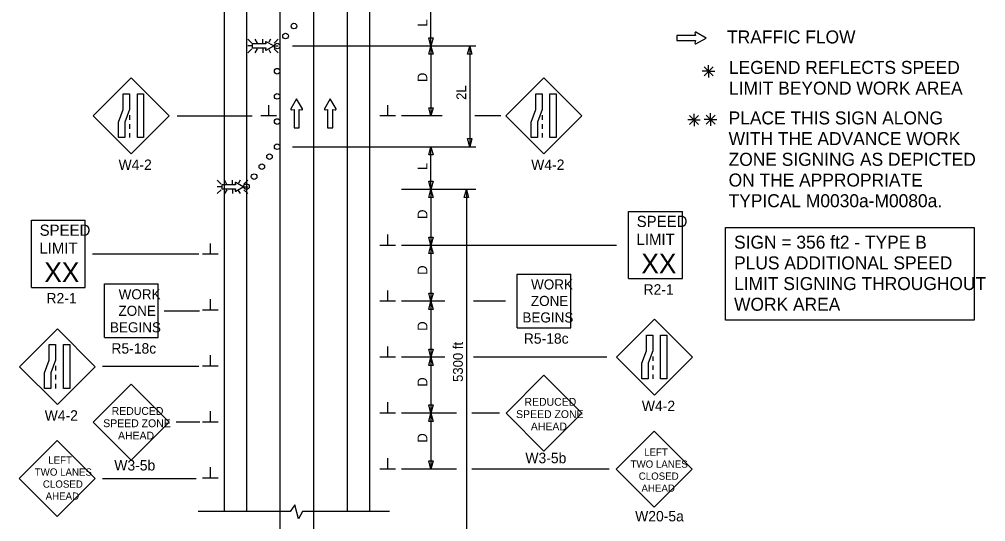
# Model space of a CAD drawing. Extents: x 16553 to 18475, y 5759 to 7026.
# Drawn here: x 16725 to 17417, y 6273 to 6632 of the extents above; entities that cross this region are included whole.
import ezdxf

# ---------------------------------------------------------------- set-up
doc = ezdxf.new("R2010")
doc.units = 0
for name, color, linetype in [('ALI_LEGAL_EX', 7, 'Continuous'), ('MT_SCRATCH_LEVEL_E', 7, 'Continuous'), ('PAVT_EDGE_EX', 7, 'Continuous'), ('TRAFFIC_SIGNS_PR', 7, 'Continuous'), ('TYPICAL_TEXT_DIMEN_EX', 7, 'Continuous'), ('TYPICAL_TEXT_DIMEN_PR', 7, 'Continuous')]:
    doc.layers.add(name, color=color, linetype=linetype)

msp = doc.modelspace()

# ---------------------------------------------------------------- linework, layer by layer
at = {"layer": 'ALI_LEGAL_EX'}
for p, q in [((16911.66, 7026.35), (16911.66, 6197.16)), ((16935.66, 7026.35), (16935.66, 6197.16)), ((16935.66, 7026.35), (16935.66, 6197.16))]:
    msp.add_line(p, q, dxfattribs=at)
for points in [[(16911.66, 6575.78), (16911.66, 6550.78)], [(16935.66, 6575.78), (16935.66, 6550.78)], [(16911.66, 6475.78), (16911.66, 6450.78)], [(16935.66, 6475.78), (16935.66, 6450.78)], [(16911.66, 6375.78), (16911.66, 6350.78)], [(16935.66, 6375.78), (16935.66, 6350.78)]]:
    msp.add_lwpolyline(points, dxfattribs=at)
at = {"layer": 'MT_SCRATCH_LEVEL_E'}
for p, q in [((17208.96, 6620.64), (17195.71, 6620.64)), ((17195.71, 6620.64), (17195.71, 6616.9)), ((17208.65, 6622.42), (17208.96, 6620.64)), ((17216.57, 6618.79), (17209.33, 6622.9)), ((17209.33, 6614.64), (17216.57, 6618.79)), ((17195.71, 6616.9), (17208.96, 6616.9)), ((17208.96, 6616.9), (17208.65, 6615.12)), ((16923.57, 6575.4), (16919.46, 6568.15)), ((16927.71, 6568.15), (16923.57, 6575.4)), ((16947.62, 6575.4), (16943.51, 6568.15)), ((16951.77, 6568.15), (16947.62, 6575.4)), ((16919.94, 6567.47), (16921.72, 6567.79)), ((16921.72, 6567.79), (16921.72, 6554.53)), ((16925.46, 6554.53), (16925.46, 6567.79)), ((16925.46, 6567.79), (16927.23, 6567.47)), ((16943.99, 6567.47), (16945.77, 6567.79)), ((16945.77, 6567.79), (16945.77, 6554.53)), ((16949.51, 6554.53), (16949.51, 6567.79)), ((16949.51, 6567.79), (16951.29, 6567.47)), ((16921.72, 6554.53), (16925.46, 6554.53)), ((16945.77, 6554.53), (16949.51, 6554.53))]:
    msp.add_line(p, q, dxfattribs=at)
for centre, start, end in [((17209.11, 6622.49), 60.42484, 189.96381), ((17209.11, 6615.05), 170.03619, 299.77312), ((16919.86, 6567.93), 150.42484, 279.96381), ((16927.3, 6567.93), 260.03619, 29.77312), ((16943.92, 6567.93), 150.42484, 279.96381), ((16951.36, 6567.93), 260.03619, 29.77312)]:
    msp.add_arc(centre, 0.463, start, end, dxfattribs=at)
at = {"layer": 'PAVT_EDGE_EX'}
for p, q in [((16871.66, 6926.66), (16871.66, 6280.21)), ((16887.66, 6926.66), (16887.66, 6280.21)), ((16959.66, 6926.66), (16959.66, 6280.21)), ((16975.66, 6926.66), (16975.66, 6280.21))]:
    msp.add_line(p, q, dxfattribs=at)
at = {"layer": 'TRAFFIC_SIGNS_PR'}
for p, q in [((16891.44, 6615.16), (16888.62, 6617.99)), ((16893.74, 6617.98), (16895.36, 6615.16)), ((16899.52, 6615.16), (16899.52, 6617.98)), ((16904.99, 6617.98), (16903.79, 6615.89)), ((16910.43, 6617.98), (16907.61, 6615.16)), ((16891.44, 6613.13), (16888.62, 6613.13)), ((16891.44, 6611.1), (16888.62, 6608.28)), ((16895.39, 6611.1), (16893.76, 6608.28)), ((16899.52, 6611.1), (16899.52, 6608.28)), ((16907.61, 6613.13), (16910.43, 6613.13)), ((16910.43, 6608.28), (16907.61, 6611.1)), ((16903.71, 6610.47), (16904.97, 6608.28)), ((16805.2, 6590.2), (16778.05, 6563.05)), ((16832.35, 6563.05), (16805.2, 6590.2)), ((17100.49, 6590.2), (17073.34, 6563.05)), ((17127.65, 6563.05), (17100.49, 6590.2)), ((16778.05, 6563.05), (16805.2, 6535.9)), ((16803.95, 6563.54), (16803.95, 6560.34)), ((16805.2, 6535.9), (16832.35, 6563.05)), ((17073.34, 6563.05), (17100.49, 6535.89)), ((17099.25, 6563.54), (17099.25, 6560.34)), ((17100.49, 6535.89), (17127.65, 6563.05)), ((16803.95, 6557.14), (16803.95, 6553.94)), ((17099.25, 6557.14), (17099.25, 6553.94)), ((16803.95, 6550.74), (16803.95, 6547.54)), ((17099.25, 6550.74), (17099.25, 6547.54)), ((16869.6, 6514.38), (16866.78, 6517.2)), ((16871.9, 6517.2), (16873.52, 6514.38)), ((16877.68, 6514.38), (16877.68, 6517.2)), ((16883.15, 6517.2), (16881.94, 6515.1)), ((16888.59, 6517.19), (16885.77, 6514.38)), ((16869.6, 6512.34), (16866.78, 6512.34)), ((16869.6, 6510.31), (16866.78, 6507.49)), ((16873.55, 6510.31), (16871.92, 6507.49)), ((16877.68, 6510.31), (16877.68, 6507.49)), ((16881.87, 6509.68), (16883.13, 6507.49)), ((16885.77, 6512.34), (16888.59, 6512.34)), ((16888.59, 6507.49), (16885.77, 6510.31)), ((17161.17, 6494.79), (17199.62, 6494.79)), ((17161.17, 6446.73), (17161.17, 6494.79)), ((17199.62, 6446.73), (17199.62, 6494.79)), ((16733.89, 6488.51), (16772.34, 6488.51)), ((16733.89, 6440.45), (16733.89, 6488.51)), ((16772.34, 6440.45), (16772.34, 6488.51)), ((17081.34, 6411.61), (17081.34, 6450.01)), ((17081.34, 6450.01), (17119.74, 6450.01)), ((17119.74, 6411.61), (17119.74, 6450.01)), ((17161.17, 6446.73), (17199.62, 6446.73)), ((16733.89, 6440.45), (16772.34, 6440.45)), ((16786.21, 6404.56), (16786.21, 6442.96)), ((16786.21, 6442.96), (16824.61, 6442.96)), ((16824.61, 6404.56), (16824.61, 6442.96)), ((17179.68, 6417.74), (17152.52, 6390.58)), ((17206.83, 6390.58), (17179.68, 6417.74)), ((16752.35, 6410.92), (16725.2, 6383.77)), ((16779.5, 6383.77), (16752.35, 6410.92)), ((17081.34, 6411.61), (17119.74, 6411.61)), ((16786.21, 6404.56), (16824.61, 6404.56)), ((17152.52, 6390.58), (17179.68, 6363.43)), ((17178.43, 6391.08), (17178.43, 6387.88)), ((17179.68, 6363.43), (17206.83, 6390.58)), ((16725.2, 6383.77), (16752.35, 6356.62)), ((16751.1, 6384.26), (16751.1, 6381.06)), ((16752.35, 6356.62), (16779.5, 6383.77)), ((17178.43, 6384.68), (17178.43, 6381.48)), ((16751.1, 6377.86), (16751.1, 6374.66)), ((17100.59, 6377.66), (17073.44, 6350.51)), ((17127.74, 6350.51), (17100.59, 6377.66)), ((17178.43, 6378.28), (17178.43, 6375.08)), ((16751.1, 6371.46), (16751.1, 6368.26)), ((16805.17, 6371.15), (16778.01, 6343.99)), ((16832.32, 6343.99), (16805.17, 6371.15)), ((17073.44, 6350.51), (17100.59, 6323.36)), ((17100.59, 6323.36), (17127.74, 6350.51)), ((16778.01, 6343.99), (16805.17, 6316.84)), ((16805.17, 6316.84), (16832.32, 6343.99)), ((17179.5, 6337.64), (17152.34, 6310.49)), ((17206.65, 6310.49), (17179.5, 6337.64)), ((16752.3, 6331.04), (16725.15, 6303.89)), ((16779.45, 6303.89), (16752.3, 6331.04)), ((17152.34, 6310.49), (17179.5, 6283.34)), ((17179.5, 6283.34), (17206.65, 6310.49)), ((16725.15, 6303.89), (16752.3, 6276.74)), ((16752.3, 6276.74), (16779.45, 6303.89))]:
    msp.add_line(p, q, dxfattribs=at)
for points in [[(16901.35, 6615.81), (16901.58, 6614.52), (16891.86, 6614.52), (16891.86, 6611.77), (16901.58, 6611.77), (16901.35, 6610.47)], [(16901.85, 6610.12), (16907.16, 6613.13), (16901.85, 6616.17)], [(16879.51, 6515.03), (16879.74, 6513.73), (16870.02, 6513.73), (16870.02, 6510.99), (16879.74, 6510.99), (16879.51, 6509.68)], [(16880.01, 6509.33), (16885.32, 6512.34), (16880.01, 6515.39)]]:
    msp.add_lwpolyline(points, dxfattribs=at)
for points in [[(16803.95, 6578.79), (16803.95, 6567.61), (16800.61, 6558.72), (16800.61, 6547.54), (16796.11, 6547.54), (16796.11, 6558.72), (16799.46, 6567.61), (16799.46, 6578.79)], [(16814.09, 6578.79), (16814.09, 6547.54), (16809.6, 6547.54), (16809.6, 6578.79)], [(17099.25, 6578.78), (17099.25, 6567.6), (17095.9, 6558.72), (17095.9, 6547.54), (17091.41, 6547.54), (17091.41, 6558.72), (17094.75, 6567.6), (17094.75, 6578.78)], [(17109.38, 6578.78), (17109.38, 6547.54), (17104.89, 6547.54), (17104.89, 6578.78)], [(17178.43, 6406.32), (17178.43, 6395.14), (17175.09, 6386.26), (17175.09, 6375.08), (17170.59, 6375.08), (17170.59, 6386.26), (17173.94, 6395.14), (17173.94, 6406.32)], [(17188.57, 6406.32), (17188.57, 6375.08), (17184.07, 6375.08), (17184.07, 6406.32)], [(16751.1, 6399.51), (16751.1, 6388.33), (16747.76, 6379.44), (16747.76, 6368.26), (16743.27, 6368.26), (16743.27, 6379.44), (16746.61, 6388.33), (16746.61, 6399.51)], [(16761.24, 6399.51), (16761.24, 6368.26), (16756.75, 6368.26), (16756.75, 6399.51)]]:
    msp.add_lwpolyline(points, close=True, dxfattribs=at)
for centre in [(16921.66, 6627.34), (16915.66, 6620.2), (16909.66, 6613.06), (16909.66, 6595.06), (16909.66, 6577.06), (16909.66, 6559.06), (16909.66, 6541.06), (16904.17, 6533.93), (16898.67, 6526.8), (16893.17, 6519.67), (16887.67, 6512.55)]:
    msp.add_circle(centre, 2, dxfattribs=at)
for centre, start, end in [((16901.69, 6615.87), 61.48329, 189.95933), ((16901.69, 6610.42), 170.73078, 298.89165), ((16879.85, 6515.08), 61.48329, 189.95933), ((16879.85, 6509.63), 170.73078, 298.89165)]:
    msp.add_arc(centre, 0.341, start, end, dxfattribs=at)
at = {"layer": 'TYPICAL_TEXT_DIMEN_EX'}
msp.add_lwpolyline([(17230.4, 6483.23), (17408.49, 6483.23), (17408.49, 6416.91), (17230.4, 6416.91)], close=True, dxfattribs=at)
at = {"layer": 'TYPICAL_TEXT_DIMEN_PR'}
for p, q in [((17019.66, 6613.06), (17019.66, 6643.62)), ((17019.66, 6613.06), (17018.09, 6618.92)), ((17018.09, 6618.92), (17019.66, 6618.92)), ((17019.66, 6618.92), (17021.23, 6618.92)), ((17021.23, 6618.92), (17019.66, 6613.06)), ((17051.71, 6613.06), (16920.56, 6613.06)), ((17018.09, 6607.2), (17019.66, 6613.06)), ((17019.66, 6613.06), (17019.66, 6563.06)), ((17019.66, 6613.06), (17021.23, 6607.2)), ((17045.9, 6607.2), (17047.47, 6613.06)), ((17047.47, 6613.06), (17049.04, 6607.2)), ((17047.47, 6613.06), (17047.47, 6541.06)), ((17019.66, 6607.2), (17018.09, 6607.2)), ((17021.23, 6607.2), (17019.66, 6607.2)), ((17047.47, 6607.2), (17045.9, 6607.2)), ((17049.04, 6607.2), (17047.47, 6607.2)), ((17221.61, 6598.2), (17215.23, 6591.82)), ((17215.24, 6598.2), (17221.61, 6591.82)), ((17218.42, 6595.01), (17218.42, 6599.47)), ((17218.42, 6595.01), (17213.89, 6595.01)), ((17218.42, 6595.01), (17221.61, 6595.01)), ((17218.42, 6595.01), (17222.9, 6595.01)), ((17218.42, 6595.01), (17218.42, 6590.51)), ((16903.59, 6563.06), (16903.59, 6570.85)), ((16988.79, 6563.06), (16988.79, 6570.85)), ((16838.06, 6563.06), (16891.86, 6563.06)), ((16909.22, 6563.06), (16897.97, 6563.06)), ((16994.41, 6563.06), (16983.16, 6563.06)), ((17027.77, 6563.06), (16998.66, 6563.06)), ((17019.66, 6563.06), (17018.09, 6568.92)), ((17018.09, 6568.92), (17019.66, 6568.92)), ((17019.66, 6568.92), (17021.23, 6568.92)), ((17021.23, 6568.92), (17019.66, 6563.06)), ((17047.47, 6567.93), (17047.47, 6564.16)), ((17069.8, 6563.06), (17051.1, 6563.06)), ((17204.77, 6563.41), (17211.14, 6557.04)), ((17211.14, 6563.41), (17204.77, 6557.04)), ((17207.95, 6560.23), (17207.95, 6564.68)), ((17216.6, 6563.68), (17222.98, 6557.3)), ((17222.98, 6563.68), (17216.6, 6557.3)), ((17219.79, 6560.49), (17219.79, 6564.95)), ((17207.95, 6560.23), (17203.42, 6560.23)), ((17207.95, 6560.23), (17211.14, 6560.23)), ((17207.95, 6560.23), (17212.43, 6560.23)), ((17207.95, 6560.23), (17207.95, 6555.73)), ((17219.79, 6560.49), (17215.26, 6560.49)), ((17219.79, 6560.49), (17222.98, 6560.49)), ((17219.79, 6560.49), (17224.27, 6560.49)), ((17219.79, 6560.49), (17219.79, 6555.99)), ((17047.47, 6541.06), (17045.9, 6546.92)), ((17045.9, 6546.92), (17047.47, 6546.92)), ((17047.47, 6546.92), (17049.04, 6546.92)), ((17049.04, 6546.92), (17047.47, 6541.06)), ((16920.56, 6541.06), (17051.71, 6541.06)), ((17018.09, 6535.2), (17019.66, 6541.06)), ((17019.66, 6535.2), (17018.09, 6535.2)), ((17019.66, 6510.5), (17019.66, 6541.06)), ((17019.66, 6541.06), (17021.23, 6535.2)), ((17021.23, 6535.2), (17019.66, 6535.2)), ((17019.66, 6510.5), (17018.09, 6516.36)), ((17018.09, 6516.36), (17019.66, 6516.36)), ((17019.66, 6516.36), (17021.23, 6516.36)), ((17021.23, 6516.36), (17019.66, 6510.5)), ((17051.71, 6510.5), (16998.66, 6510.5)), ((17018.09, 6504.64), (17019.66, 6510.5)), ((17019.66, 6510.5), (17019.66, 6470.5)), ((17019.66, 6510.5), (17021.23, 6504.64)), ((17043.53, 6504.64), (17045.1, 6510.5)), ((17045.1, 6510.5), (17045.1, 6235.04)), ((17045.1, 6510.5), (17046.67, 6504.64)), ((17019.66, 6504.64), (17018.09, 6504.64)), ((17021.23, 6504.64), (17019.66, 6504.64)), ((17045.1, 6504.64), (17043.53, 6504.64)), ((17046.67, 6504.64), (17045.1, 6504.64)), ((16988.79, 6470.5), (16988.79, 6478.28)), ((17019.66, 6470.5), (17018.09, 6476.36)), ((17018.09, 6476.36), (17019.66, 6476.36)), ((17019.66, 6476.36), (17021.23, 6476.36)), ((17021.23, 6476.36), (17019.66, 6470.5)), ((16861.91, 6464.15), (16861.91, 6471.94)), ((16994.41, 6470.5), (16983.16, 6470.5)), ((17050.1, 6470.5), (16998.66, 6470.5)), ((17018.09, 6464.63), (17019.66, 6470.5)), ((17019.66, 6470.5), (17019.66, 6430.5)), ((17019.66, 6470.5), (17021.23, 6464.63)), ((17152.57, 6470.5), (17050.1, 6470.5)), ((16853.58, 6464.22), (16777.59, 6464.22)), ((16867.54, 6464.15), (16856.29, 6464.15)), ((17019.66, 6464.63), (17018.09, 6464.63)), ((17021.23, 6464.63), (17019.66, 6464.63)), ((16988.79, 6430.5), (16988.79, 6438.28)), ((16861.91, 6424.15), (16861.91, 6431.94)), ((17019.66, 6430.5), (17018.09, 6436.36)), ((17018.09, 6436.36), (17019.66, 6436.36)), ((17019.66, 6436.36), (17021.23, 6436.36)), ((17021.23, 6436.36), (17019.66, 6430.5)), ((16994.41, 6430.5), (16983.16, 6430.5)), ((17029.57, 6430.5), (16998.66, 6430.5)), ((17018.09, 6424.63), (17019.66, 6430.5)), ((17019.66, 6424.63), (17018.09, 6424.63)), ((17019.66, 6430.5), (17019.66, 6390.5)), ((17019.66, 6430.5), (17021.23, 6424.63)), ((17021.23, 6424.63), (17019.66, 6424.63)), ((17073.14, 6430.5), (17050.16, 6430.5)), ((16854.16, 6423.44), (16828.8, 6423.44)), ((16867.54, 6424.15), (16856.29, 6424.15)), ((16988.79, 6390.5), (16988.79, 6398.28)), ((16861.91, 6384.15), (16861.91, 6391.94)), ((16994.41, 6390.5), (16983.16, 6390.5)), ((17029.57, 6390.5), (16998.66, 6390.5)), ((17019.66, 6390.5), (17018.09, 6396.36)), ((17018.09, 6396.36), (17019.66, 6396.36)), ((17018.09, 6384.63), (17019.66, 6390.5)), ((17019.66, 6396.36), (17021.23, 6396.36)), ((17021.23, 6396.36), (17019.66, 6390.5)), ((17019.66, 6390.5), (17019.66, 6350.5)), ((17019.66, 6390.5), (17021.23, 6384.63)), ((17145.55, 6390.5), (17050.1, 6390.5)), ((16853.65, 6383.8), (16784.75, 6383.8)), ((16867.54, 6384.15), (16856.29, 6384.15)), ((17019.66, 6384.63), (17018.09, 6384.63)), ((17021.23, 6384.63), (17019.66, 6384.63)), ((16988.79, 6350.5), (16988.79, 6358.28)), ((17019.66, 6350.5), (17018.09, 6356.36)), ((17018.09, 6356.36), (17019.66, 6356.36)), ((17019.66, 6356.36), (17021.23, 6356.36)), ((17021.23, 6356.36), (17019.66, 6350.5)), ((16861.91, 6344.15), (16861.91, 6351.94)), ((16994.41, 6350.5), (16983.16, 6350.5)), ((17038.03, 6350.5), (16998.66, 6350.5)), ((17018.09, 6344.63), (17019.66, 6350.5)), ((17019.66, 6350.5), (17019.66, 6310.49)), ((17019.66, 6350.5), (17021.23, 6344.63)), ((17068.73, 6350.5), (17049.01, 6350.5)), ((16854.42, 6344.02), (16837.48, 6344.02)), ((16867.54, 6344.15), (16856.29, 6344.15)), ((17019.66, 6344.63), (17018.09, 6344.63)), ((17021.23, 6344.63), (17019.66, 6344.63)), ((16988.79, 6310.5), (16988.79, 6318.28)), ((17019.66, 6310.49), (17018.09, 6316.36)), ((17018.09, 6316.36), (17019.66, 6316.36)), ((17019.66, 6316.36), (17021.23, 6316.36)), ((17021.23, 6316.36), (17019.66, 6310.49)), ((16861.91, 6304.15), (16861.91, 6311.94)), ((16994.41, 6310.5), (16983.16, 6310.5)), ((17038.03, 6310.49), (16998.66, 6310.49)), ((17147.29, 6310.49), (17049.01, 6310.49)), ((16784.75, 6303.87), (16851.75, 6303.87)), ((16867.54, 6304.15), (16856.29, 6304.15)), ((16919.01, 6280.21), (16853.07, 6280.21)), ((16922.27, 6285.01), (16919.01, 6280.21)), ((16925.01, 6275.07), (16922.27, 6285.01)), ((16927.75, 6280.21), (16925.01, 6275.07)), ((16990.08, 6280.21), (16927.75, 6280.21))]:
    msp.add_line(p, q, dxfattribs=at)
msp.add_open_spline([(17311.37, 6595.6), (17311.39, 6595.6), (17311.4, 6595.6), (17311.4, 6595.6)], degree=2, dxfattribs=at)

# ---------------------------------------------------------------- texts
at = {"layer": 'TRAFFIC_SIGNS_PR'}
for s, height, p in [('W4-2', 7.44, (16796.16, 6524.46)), ('W4-2', 7.44, (17091.45, 6524.45)), ('SPEED', 8.01, (17166.94, 6483.64)), ('SPEED', 8.01, (16739.67, 6477.36)), ('LIMIT', 8.01, (17166.78, 6470.82)), ('LIMIT', 8.01, (16739.5, 6464.55)), ('XX', 14.048, (17170.29, 6450.49)), ('XX', 14.048, (16743.02, 6444.22)), ('WORK', 7.217, (17091.34, 6438.98)), ('WORK', 7.217, (16796.21, 6431.93)), ('R2-1', 7.449, (17171.86, 6435.28)), ('R2-1', 7.449, (16744.58, 6429)), ('ZONE', 7.217, (17091.22, 6427.17)), ('ZONE', 7.217, (16796.09, 6420.12)), ('BEGINS', 7.217, (17085.15, 6415.36)), ('BEGINS', 7.217, (16790.02, 6408.31)), ('R5-18c', 7.44, (17086.15, 6400.18)), ('R5-18c', 7.44, (16791.02, 6393.12)), ('REDUCED', 5.6, (17086.65, 6355.82)), ('W4-2', 7.44, (17170.63, 6351.99)), ('W4-2', 7.44, (16743.31, 6345.18)), ('REDUCED', 5.6, (16791.22, 6349.3)), ('SPEED ZONE', 5.6, (17080.64, 6347.02)), ('SPEED ZONE', 5.6, (16785.22, 6340.5)), ('AHEAD', 5.6, (17091.2, 6338.22)), ('AHEAD', 5.6, (16795.78, 6331.7)), ('W3-5b', 7.44, (17087.29, 6314.74)), ('LEFT', 5.2, (17172.23, 6320.1)), ('LEFT', 5.2, (16745.84, 6314.42)), ('W3-5b', 7.44, (16793.12, 6309.52)), ('TWO LANES', 5.2, (17162.55, 6311.5)), ('TWO LANES', 5.2, (16736.16, 6305.82)), ('CLOSED', 5.2, (17168.4, 6302.9)), ('CLOSED', 5.2, (16742.01, 6297.22)), ('AHEAD', 5.2, (16743.96, 6288.62)), ('AHEAD', 5.2, (17170.35, 6294.3)), ('W20-5a', 7.44, (17165.84, 6273.13))]:
    msp.add_text(s, height=height, dxfattribs=at).set_placement(p)
at = {"layer": 'TYPICAL_TEXT_DIMEN_EX'}
for s, p in [('TRAFFIC FLOW', (17231.64, 6614.91)), ('LEGEND REFLECTS SPEED', (17232.97, 6593.11)), ('LIMIT BEYOND WORK AREA', (17232.97, 6578.31)), ('PLACE THIS SIGN ALONG', (17232.73, 6556.99)), ('WITH THE ADVANCE WORK', (17232.73, 6542.19)), ('ZONE SIGNING AS DEPICTED', (17232.73, 6527.39)), ('ON THE APPROPRIATE', (17232.73, 6512.59)), ('TYPICAL M0030a-M0080a.', (17232.73, 6497.79)), ('SIGN = 356 ft2 - TYPE B', (17236.63, 6468.15)), ('PLUS ADDITIONAL SPEED', (17236.63, 6453.35)), ('LIMIT SIGNING THROUGHOUT', (17236.63, 6438.55)), ('WORK AREA', (17236.63, 6423.75))]:
    msp.add_text(s, height=9.3, dxfattribs=at).set_placement(p)
at = {"layer": 'TYPICAL_TEXT_DIMEN_PR'}
for s, p in [('L', (17017.1, 6626.92)), ('D', (17017.1, 6587.28)), ('2L', (17044.91, 6574.56)), ('L', (17017.1, 6524.35)), ('D', (17017.11, 6489.41)), ('D', (17017.11, 6449.41)), ('D', (17017.11, 6409.41)), ('5300 ft', (17042.55, 6372.86)), ('D', (17017.11, 6369.41)), ('D', (17017.11, 6329.41))]:
    msp.add_text(s, height=7, rotation=90, dxfattribs=at).set_placement(p)

doc.saveas('drawing.dxf')
